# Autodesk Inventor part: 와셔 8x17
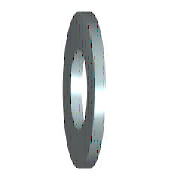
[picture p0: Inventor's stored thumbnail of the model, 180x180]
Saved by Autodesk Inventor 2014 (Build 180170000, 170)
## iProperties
IsCustomPart: 1
Created: 2012-02
Part Number: 와셔 8x17
Material: 강철, 연강
Description: 평면 와셔
Document SubType Name: Modeling
Standard: KS B 1326
Designer: mduedu
Standards Organization: KS
Language: ko-KR
Size Designation: 8x17
Categories: <MemberInstance><Categories><Category DisplayName="조임쇠" InternalName="e4da775c-781d-43d5-af7c-5136215cf5a6" Mnemonic="FSTN"><Category DisplayName="와셔" InternalN
Density: 1 g/cm^3
Appearance: 주황색
Author: mduedu
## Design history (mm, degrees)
sketch "스케치"
  geometry: C1 r 8.5 at (0, 0); C2 r 4.2 at (0, 0); 1 further point
  constraints: 2 centre point, 2 coincident
  dimensions: "d0" = 8.4 diameter of C2 (= SD1); "d1" = 17 diameter of C1 (= SD2)
extrude "본체" new body sketch "스케치" distance "d2" = 1.6 (= SD); taper "d3" = 0 deg
workaxis "Work Axis1"
workplane "Work Plane1"
body "Solid1"
other parameters: "SD1" = 8.4 [user parameter; used in 1 equation term], "SD2" = 17 [user parameter; used in 1 equation term], "SD" = 1.6 [user parameter; used in 1 equation term], "d4" = 0, "d5" = 0, "d6" = 0, "d7" = 0, "NND" = 8 [user parameter]
